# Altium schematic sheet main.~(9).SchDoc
size A
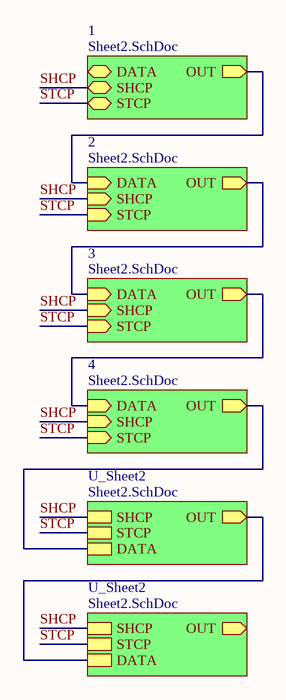
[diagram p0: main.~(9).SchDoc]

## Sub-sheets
1 = Sheet2.SchDoc: DATA, SHCP, STCP, OUT (out)
2 = Sheet2.SchDoc: DATA (in), SHCP (in), STCP (in), OUT (out)
3 = Sheet2.SchDoc: DATA (in), SHCP (in), STCP (in), OUT (out)
4 = Sheet2.SchDoc: DATA (in), SHCP (in), STCP (in), OUT (out)
U_Sheet2 = Sheet2.SchDoc: SHCP, STCP, DATA, OUT (out)
U_Sheet2 = Sheet2.SchDoc: SHCP, STCP, DATA, OUT (out)

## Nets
SHCP: sheet 1/SHCP, sheet 2/SHCP, sheet 3/SHCP, sheet 4/SHCP, sheet U_Sheet2/SHCP, sheet U_Sheet2/SHCP
STCP: sheet 1/STCP, sheet 2/STCP, sheet 3/STCP, sheet 4/STCP, sheet U_Sheet2/STCP, sheet U_Sheet2/STCP
(unnamed): sheet 1/OUT, sheet 2/DATA
(unnamed): sheet 2/OUT, sheet 3/DATA  [a separate net that carries the same name]
(unnamed): sheet 3/OUT, sheet 4/DATA  [a separate net that carries the same name]
(unnamed): sheet 4/OUT, sheet U_Sheet2/DATA  [a separate net that carries the same name]
(unnamed): sheet U_Sheet2/OUT, sheet U_Sheet2/DATA  [a separate net that carries the same name]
